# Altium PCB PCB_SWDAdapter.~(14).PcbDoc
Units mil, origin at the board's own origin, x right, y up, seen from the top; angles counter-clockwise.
Board outline 1010 x 725 mil, 2 copper layers (Top Layer, Bottom Layer); 3 components, 6 nets, 18 pads, 0 vias.
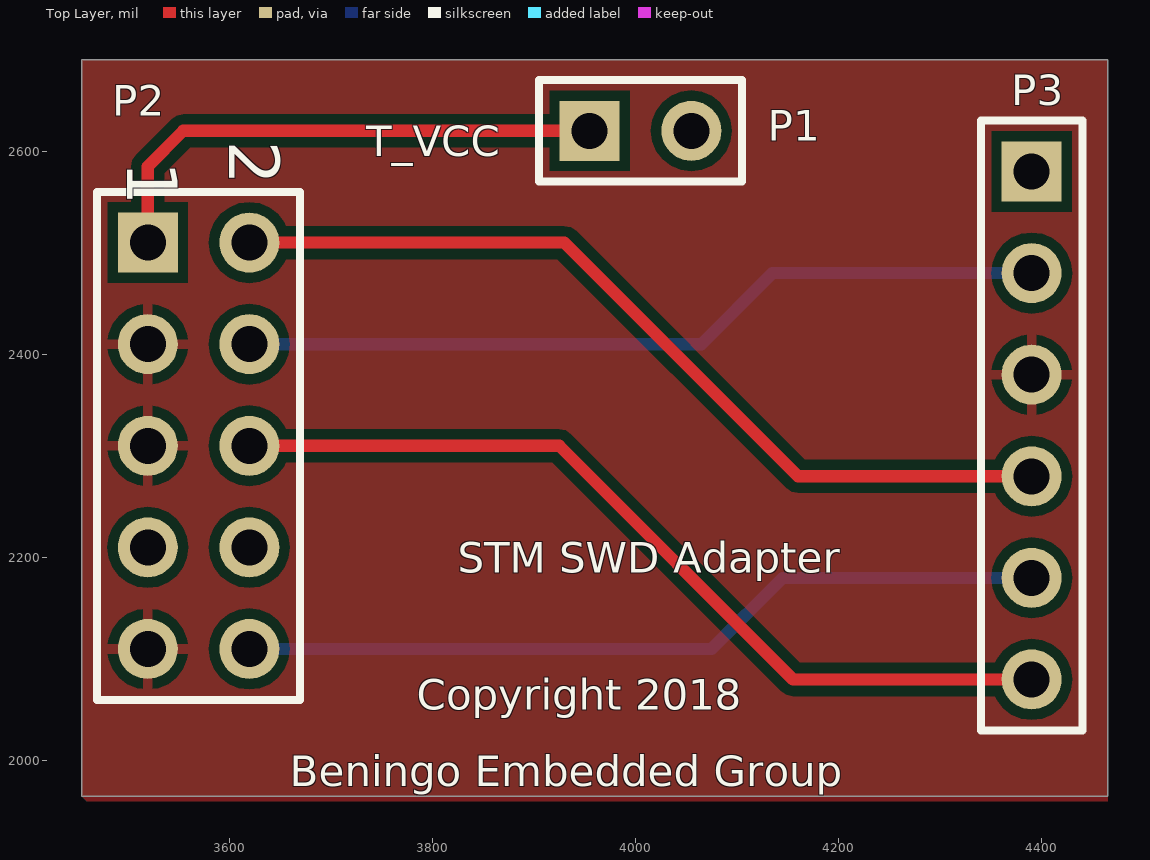
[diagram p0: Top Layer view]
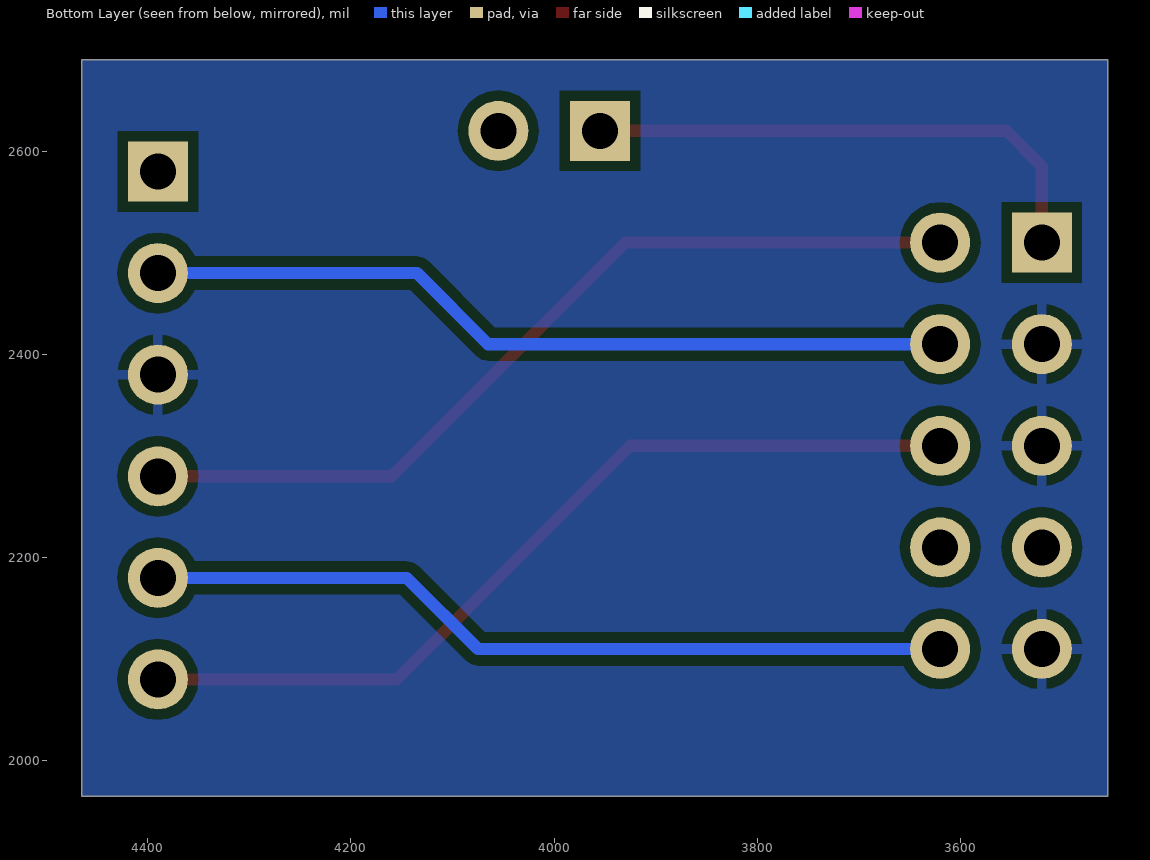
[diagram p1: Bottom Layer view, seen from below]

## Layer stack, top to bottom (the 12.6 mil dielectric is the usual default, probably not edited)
Top Solder: solder mask 0.4, Solder Resist, Dk 3.5
Top Layer: signal copper 1.4
Dielectric 1: dielectric 12.6, FR-4, Dk 4.8
Bottom Layer: signal copper 1.4
Bottom Solder: solder mask 0.4, Solder Resist, Dk 3.5

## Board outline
3455,1965 4465,1965 4465,2690 3455,2690

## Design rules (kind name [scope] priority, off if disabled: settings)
Clearance [All] p1: gap=10
PolygonConnect [All] p1: connectstyle=Relief reliefconductorwidth=10 reliefentries=4 polygonreliefangle="90 Angle" airgapwidth=10
RoutingVias [All] p1: holewidth=28 width=50 viastyle="Through Hole" minholewidth=28 minwidth=50 maxholewidth=28 maxwidth=50
SolderMaskExpansion [All] p1: expansion=4
Width [All] p1: maxlimit=20 minlimit=10 preferedwidth=10 minimp=50.000000 maximp=50.000000 favimp=50.000000
30 further rules are at their usual default settings.

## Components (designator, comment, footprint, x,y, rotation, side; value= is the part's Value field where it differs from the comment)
P1 "Target VDD" HDR1X2 3955,2620 r0 top
P2 "ARM 10-Pin SWD" HDR2X5 3520,2510 r270 top
P3 "SWD Target" HDR1X6 4390,2580 r270 top

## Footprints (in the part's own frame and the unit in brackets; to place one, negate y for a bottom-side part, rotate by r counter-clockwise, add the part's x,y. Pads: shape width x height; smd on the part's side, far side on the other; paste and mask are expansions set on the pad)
HDR1X2 [mm] "Connector; Header; 2 Position"
  rect 1.5x1.5 hole 0.9: 1(0,0)
  round 1.5 hole 0.9: 2(2.54,0)
  silkscreen extent -1.27,-1.27 3.81,1.27
HDR1X6 [mm] "Connector; Header; 6 Position"
  rect 1.5x1.5 hole 0.9: 1(0,0)
  round 1.5 hole 0.9: 2(2.54,0) 3(5.08,0) 4(7.62,0) 5(10.16,0) 6(12.7,0)
  silkscreen extent -1.27,-1.27 13.97,1.27
HDR2X5 [mm] "Connector; Header; 5x2 Position"
  rect 1.5x1.5 hole 0.9: 1(0,0)
  round 1.5 hole 0.9: 2(0,2.54) 3(2.54,0) 4(2.54,2.54) 5(5.08,0) 6(5.08,2.54) 7(7.62,0) 8(7.62,2.54) 9(10.16,0) 10(10.16,2.54)
  silkscreen extent -1.27,-1.27 11.43,3.81

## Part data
P1: library part "Header 2", "Header, 2-Pin"
P2: library part "Header 5X2", "Header, 5-Pin, Dual row"
P3: library part "Header 6", "Header, 6-Pin"

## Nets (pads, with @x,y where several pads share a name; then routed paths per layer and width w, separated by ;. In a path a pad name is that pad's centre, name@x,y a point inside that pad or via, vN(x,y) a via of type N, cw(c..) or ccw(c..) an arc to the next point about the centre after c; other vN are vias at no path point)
GND: P2.3 P2.5 P2.9 P3.3
NRST: P2.10 P3.5 | length 799
  Bottom Layer w12: P2.10 4075,2110 4145,2180 P3.5
SWCLK: P2.4 P3.2 | length 799
  Bottom Layer w12: P2.4 4065,2410 4135,2480 P3.2
SWDIO: P2.2 P3.4 | length 865.3
  Top Layer w12: P2.2 3930,2510 4160,2280 P3.4
SWO: P2.6 P3.6 | length 865.3
  Top Layer w12: P2.6 3925,2310 4155,2080 P3.6
TARGETVCC: P1.1 P2.1 | length 524.5
  Top Layer w12: P2.1 3520,2585 3555,2620 P1.1
pads on no net: P1.2 P2.7 P2.8 P3.1

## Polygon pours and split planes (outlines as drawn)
GND on Bottom Layer "BottomPout" (solid, remove dead copper, pour order 4): 3455,2690 4465,2690 4465,1965 3455,1965
GND on Top Layer "BottomPout" (solid, remove dead copper, pour order 6): 3455,2690 4465,2690 4465,1960 3460,1960 3455,1965

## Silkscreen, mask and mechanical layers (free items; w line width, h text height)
Top Overlay:
  text "T_VCC" at 3735,2595 h30
  text "STM SWD Adapter" at 3825,2185 h30
  text "Copyright 2018" at 3785,2050 h30
  text "Beningo Embedded Group" at 3660,1975 h30
Mechanical 1:
  the board outline again, w10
